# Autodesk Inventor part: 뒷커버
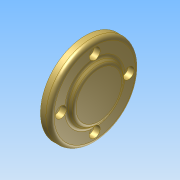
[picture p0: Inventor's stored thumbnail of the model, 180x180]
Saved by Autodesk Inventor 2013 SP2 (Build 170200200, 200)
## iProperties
Created: 2025-05
Part Number: 뒷커버
Material: Generic
Document SubType Name: Modeling
Designer: a
Density: 1 g/cm^3
Author: a
변환 표준: STEP AP214IS
전처리기: Build: 200, Release: 2013 SP2 Update 6 - Date: Thu 07/17/2014
전송 단위: 밀리미터
불확실성: 0.01
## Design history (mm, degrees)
node "뒷커버1"
node "솔리드1"
node "기준1"
